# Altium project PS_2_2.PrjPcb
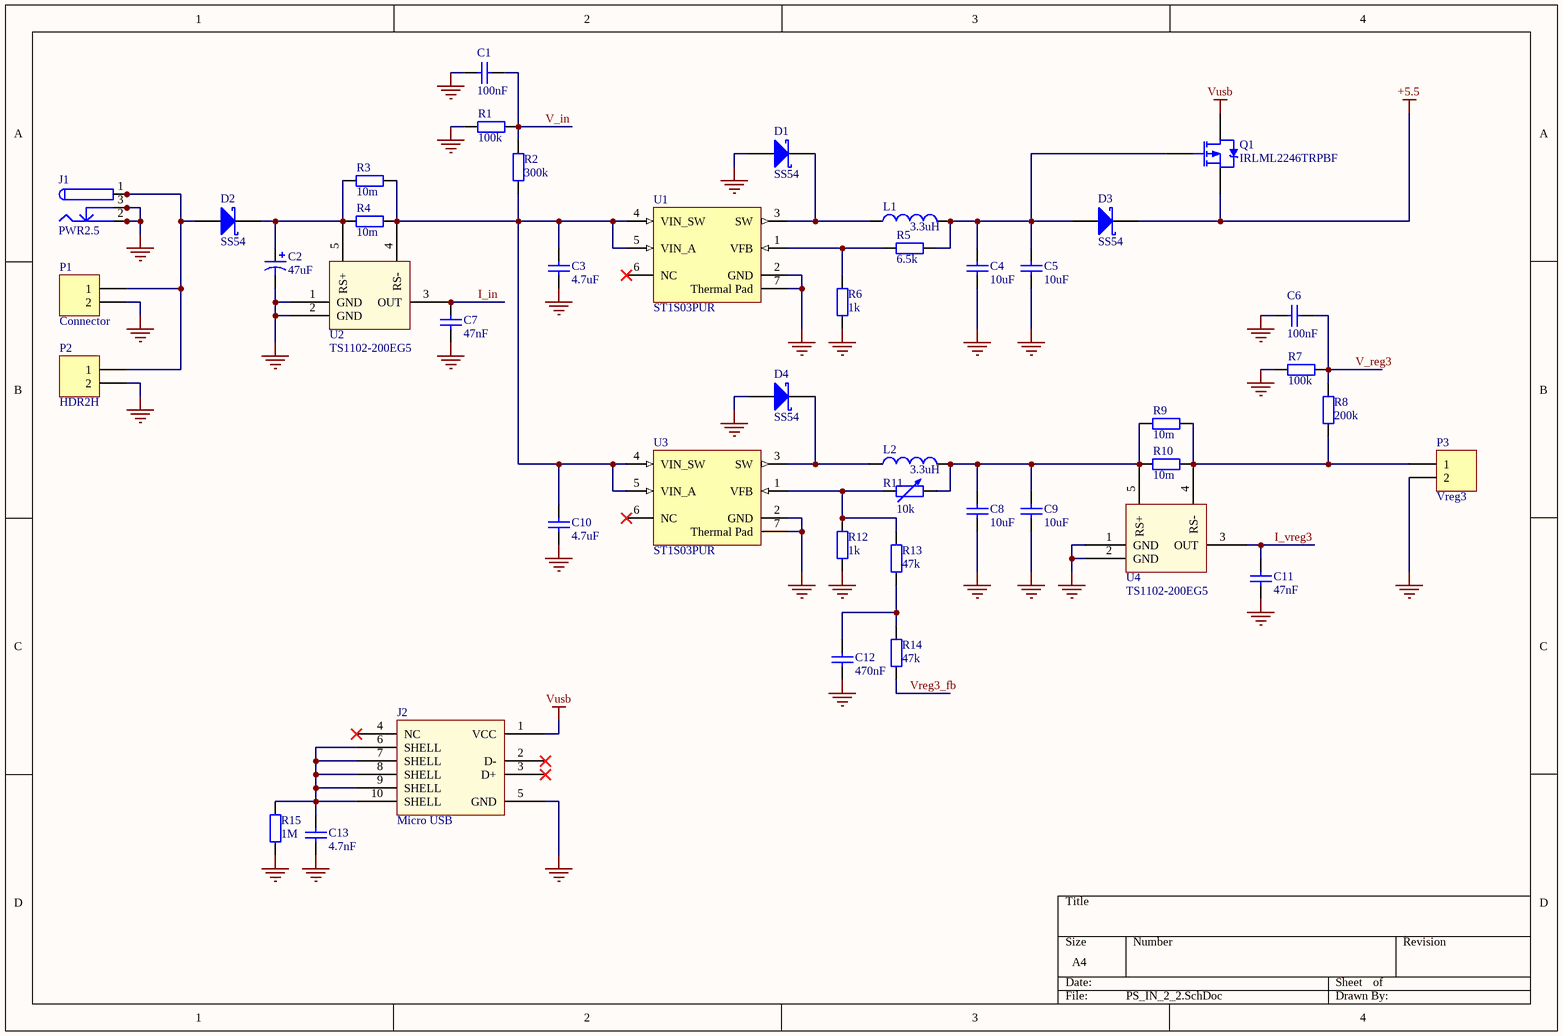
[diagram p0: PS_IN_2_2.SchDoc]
2 sheets, 82 parts. Net scope: global (net labels, ports and power ports of the same name join across sheets).
Board file: PS_2_2.PcbDoc
Sheets:
  PS_IN_2_2.SchDoc
  PS_OUT_2_2.SchDoc

## Sheet PS_IN_2_2.SchDoc
size A4

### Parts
C1  100nF  [SMD0603-C_L]
C2  47uF  [SMD4x5.5-C]
C3  4.7uF  [SMD0805-C_N]
C4  10uF  [SMD0805-C_N]
C5  10uF  [SMD0805-C_N]
C6  100nF  [SMD0603-C_L]
C7  47nF  [SMD0603-C_L]
C8  10uF  [SMD0805-C_N]
C9  10uF  [SMD0805-C_N]
C10  4.7uF  [SMD0805-C_N]
C11  47nF  [SMD0603-C_L]
C12  470nF  [SMD0603-C_L]
C13  4.7nF  [SMD0603-C_L]
D1  SS54  [DO-214AB]
D2  SS54  [DO-214AB]
D3  SS54  [DO-214AB]
D4  SS54  [DO-214AB]
J1  PWR2.5  [PWR_BARREL]
J2  Micro USB  [MICRO USB]
L1  3.3uH  [SMD1515-L]
L2  3.3uH  [SMD1515-L]
P1  Connector  [TERM_BLOCK 2]
P2  HDR2H  [CONN 1X2H]
P3  Vreg3  [CONN 1X2H]
Q1  IRLML2246TRPBF  [SOT-23 - at]
R1  100k  [SMD0603-R_L]
R2  300k  [SMD0603-R_L]
R3  10m  [RES_PCB]
R4  10m  [SMD1206-R_N]
R5  6.5k  [SMD0603-R_L]
R6  1k  [SMD0603-R_L]
R7  100k  [SMD0603-R_L]
R8  200k  [SMD0603-R_L]
R9  10m  [RES_PCB]
R10  10m  [SMD1206-R_N]
R11  10k  [PTV09A]
R12  1k  [SMD0603-R_L]
R13  47k  [SMD0603-R_L]
R14  47k  [SMD0603-R_L]
R15  1M  [SMD0603-R_L]
U1  ST1S03PUR  [DFN6D_M]
U2  TS1102-200EG5  [SOT23-5_N]
U3  ST1S03PUR  [DFN6D_M]
U4  TS1102-200EG5  [SOT23-5_N]

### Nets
+5.5: D3.2(K) Q1.3(S)
GND: C1.1 C2.2 C3.1 C4.1 C5.1 C6.1 C7.1 C8.1 C9.1 C10.1 C11.1 C12.1 C13.1 D1.1(A) D4.1(A) J1.2 J1.2A J1.2B J1.3 J1.3A J1.3B J2.5(GND) P1.2 P2.2 P3.2 R1.2 R6.1 R7.2 R12.1 R15.1 U1.2(GND) U1.7(Thermal_Pad) U2.1(GND) U2.2(GND) U3.2(GND) U3.7(Thermal_Pad) U4.1(GND) U4.2(GND)
Vusb: J2.1(VCC) Q1.2(D)
I_in: C7.2 U2.3(OUT)
I_vreg3: C11.2 U4.3(OUT)
V_in: C1.2 R1.1 R2.2
V_reg3: C6.2 R7.1 R8.2
Vreg3_fb: R14.2
NetC2_1: C2.1 D2.2(K) R3.2 R4.2 U2.5(RS+)
NetC3_2: C3.2 C10.2 R2.1 R3.1 R4.1 U1.4(VIN_SW) U1.5(VIN_A) U2.4(RS-) U3.4(VIN_SW) U3.5(VIN_A)
NetC4_2: C4.2 C5.2 D3.1(A) L1.2 Q1.1(G) R5.1
NetC8_2: C8.2 C9.2 L2.2 R9.2 R10.2 R11.2 U4.5(RS+)
NetC12_2: C12.2 R13.2 R14.1
NetC13_2: C13.2 J2.6(SHELL) J2.7(SHELL) J2.8(SHELL) J2.9(SHELL) J2.10(SHELL) R15.2
NetD1_2: D1.2(K) L1.1 U1.3(SW)
NetD2_1: D2.1(A) J1.1 J1.1A J1.1B P1.1 P2.1
NetD4_2: D4.2(K) L2.1 U3.3(SW)
NetP3_1: P3.1 R8.1 R9.1 R10.1 U4.4(RS-)
NetR5_2: R5.2 R6.2 U1.1(VFB)
NetR11_1: R11.1 R12.2 R13.1 U3.1(VFB)

Not connected (* = marked no-connect by the designer): J2 2(D-)* 3(D+)* 4(NC)*; U1 6(NC)*; U3 6(NC)*

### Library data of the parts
C1 C3-C13 = Cap: Capacitor
C2 = Cap Pol3: Polarized Capacitor (Surface Mount)
D1-D4 = D Schottky: Schottky Diode
J1 = PWR2.5: Low Voltage Power Supply Connector
J2 = Micro USB: type B
L1 L2 = Inductor: Code_IEC: 1005
P1-P3 = Header 2: Header, 2-Pin
Q1 = PMOS-2: P-Channel Power MOSFET; Note: Pin 4 not drawn and electrically connected to Pin 2.
R1-R10 R12-R15 = Res2: Resistor
R11 = Res Adj2: Variable Resistor; Set Position: 0.5
U1 U3 = ST1S03PUR: 1.5 A, 1.5 MHz adjustable, step-down switching regulator, DFN6D
U2 U4 = TS1102-200EG5: High Side Current Monitor, 200 V/V

## Sheet PS_OUT_2_2.SchDoc
size A4
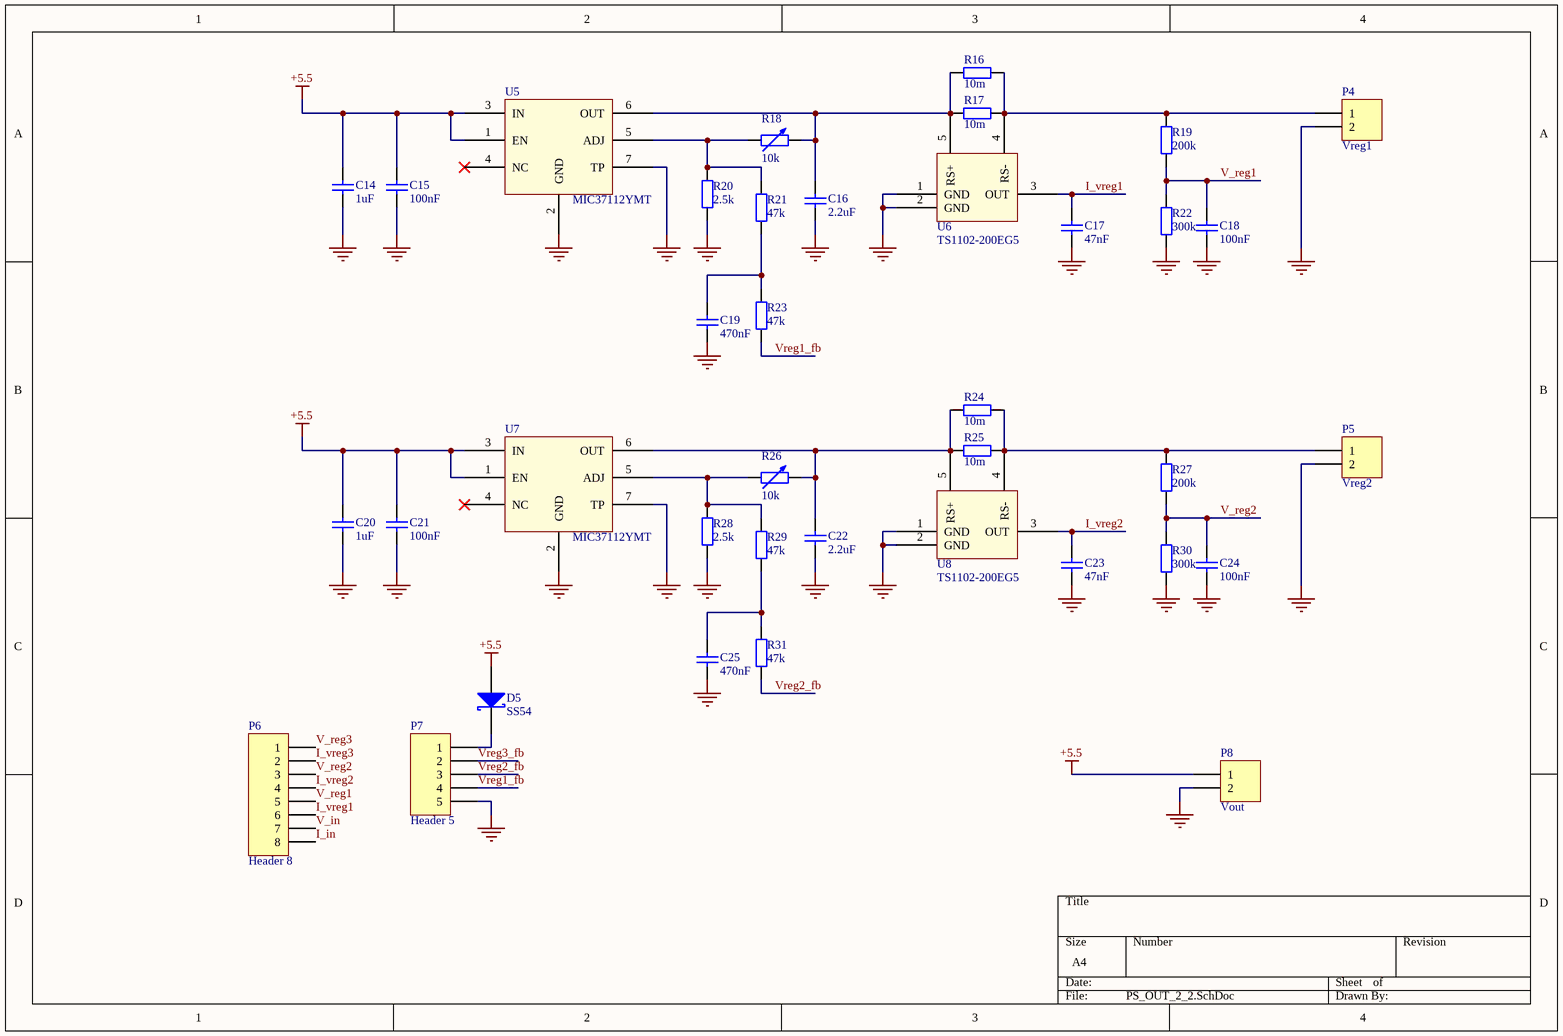
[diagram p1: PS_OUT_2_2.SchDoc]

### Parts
C14  1uF  [SMD0603-C_L]
C15  100nF  [SMD0603-C_L]
C16  2.2uF  [SMD0603-C_L]
C17  47nF  [SMD0603-C_L]
C18  100nF  [SMD0603-C_L]
C19  470nF  [SMD0603-C_L]
C20  1uF  [SMD0603-C_L]
C21  100nF  [SMD0603-C_L]
C22  2.2uF  [SMD0603-C_L]
C23  47nF  [SMD0603-C_L]
C24  100nF  [SMD0603-C_L]
C25  470nF  [SMD0603-C_L]
D5  SS54  [DO-214AB]
P4  Vreg1  [CONN 1X2H]
P5  Vreg2  [CONN 1X2H]
P6  Header 8  [HDR1X8]
P7  Header 5  [HDR1X5]
P8  Vout  [CONN 1X2H]
R16  10m  [RES_PCB]
R17  10m  [SMD1206-R_N]
R18  10k  [PTV09A]
R19  200k  [SMD0603-R_L]
R20  2.5k  [SMD0603-R_L]
R21  47k  [SMD0603-R_L]
R22  300k  [SMD0603-R_L]
R23  47k  [SMD0603-R_L]
R24  10m  [RES_PCB]
R25  10m  [SMD1206-R_N]
R26  10k  [PTV09A]
R27  200k  [SMD0603-R_L]
R28  2.5k  [SMD0603-R_L]
R29  47k  [SMD0603-R_L]
R30  300k  [SMD0603-R_L]
R31  47k  [SMD0603-R_L]
U5  MIC37112YMT  [MLF6]
U6  TS1102-200EG5  [SOT23-5_N]
U7  MIC37112YMT  [MLF6]
U8  TS1102-200EG5  [SOT23-5_N]

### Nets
+5.5: C14.2 C15.2 C20.2 C21.2 D5.1(A) P8.1 U5.1(EN) U5.3(IN) U7.1(EN) U7.3(IN)
GND: C14.1 C15.1 C16.1 C17.1 C18.1 C19.1 C20.1 C21.1 C22.1 C23.1 C24.1 C25.1 P4.2 P5.2 P7.5 P8.2 R20.1 R22.1 R28.1 R30.1 U5.2(GND) U5.7(TP) U6.1(GND) U6.2(GND) U7.2(GND) U7.7(TP) U8.1(GND) U8.2(GND)
I_in: P6.8
I_vreg1: C17.2 P6.6 U6.3(OUT)
I_vreg2: C23.2 P6.4 U8.3(OUT)
I_vreg3: P6.2
V_in: P6.7
V_reg1: C18.2 P6.5 R19.2 R22.2
V_reg2: C24.2 P6.3 R27.2 R30.2
V_reg3: P6.1
Vreg1_fb: P7.4 R23.2
Vreg2_fb: P7.3 R31.2
Vreg3_fb: P7.2
NetC16_2: C16.2 R16.2 R17.2 R18.2 U5.6(OUT) U6.5(RS+)
NetC19_2: C19.2 R21.2 R23.1
NetC22_2: C22.2 R24.2 R25.2 R26.2 U7.6(OUT) U8.5(RS+)
NetC25_2: C25.2 R29.2 R31.1
NetD5_2: D5.2(K) P7.1
NetP4_1: P4.1 R16.1 R17.1 R19.1 U6.4(RS-)
NetP5_1: P5.1 R24.1 R25.1 R27.1 U8.4(RS-)
NetR18_1: R18.1 R20.2 R21.1 U5.5(ADJ)
NetR26_1: R26.1 R28.2 R29.1 U7.5(ADJ)

Not connected (* = marked no-connect by the designer): U5 4(NC)*; U7 4(NC)*

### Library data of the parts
C14-C25 = Cap: Capacitor
D5 = D Schottky: Schottky Diode
P4 P5 P8 = Header 2: Header, 2-Pin
P6 = Header 8: Header, 8-Pin
P7 = Header 5: Header, 5-Pin
R16 R17 R19-R25 R27-R31 = Res2: Resistor
R18 R26 = Res Adj2: Variable Resistor; Set Position: 0.5
U5 U7 = MIC37112YMT: LDO, 1A
U6 U8 = TS1102-200EG5: High Side Current Monitor, 200 V/V

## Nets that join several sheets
+5.5: PS_IN_2_2 (D3.2 Q1.3), PS_OUT_2_2 (10 pins)
GND: PS_IN_2_2 (38 pins), PS_OUT_2_2 (28 pins)
I_in: PS_IN_2_2 (C7.2 U2.3), PS_OUT_2_2 (P6.8)
I_vreg3: PS_IN_2_2 (C11.2 U4.3), PS_OUT_2_2 (P6.2)
V_in: PS_IN_2_2 (C1.2 R1.1 R2.2), PS_OUT_2_2 (P6.7)
V_reg3: PS_IN_2_2 (C6.2 R7.1 R8.2), PS_OUT_2_2 (P6.1)
Vreg3_fb: PS_IN_2_2 (R14.2), PS_OUT_2_2 (P7.2)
